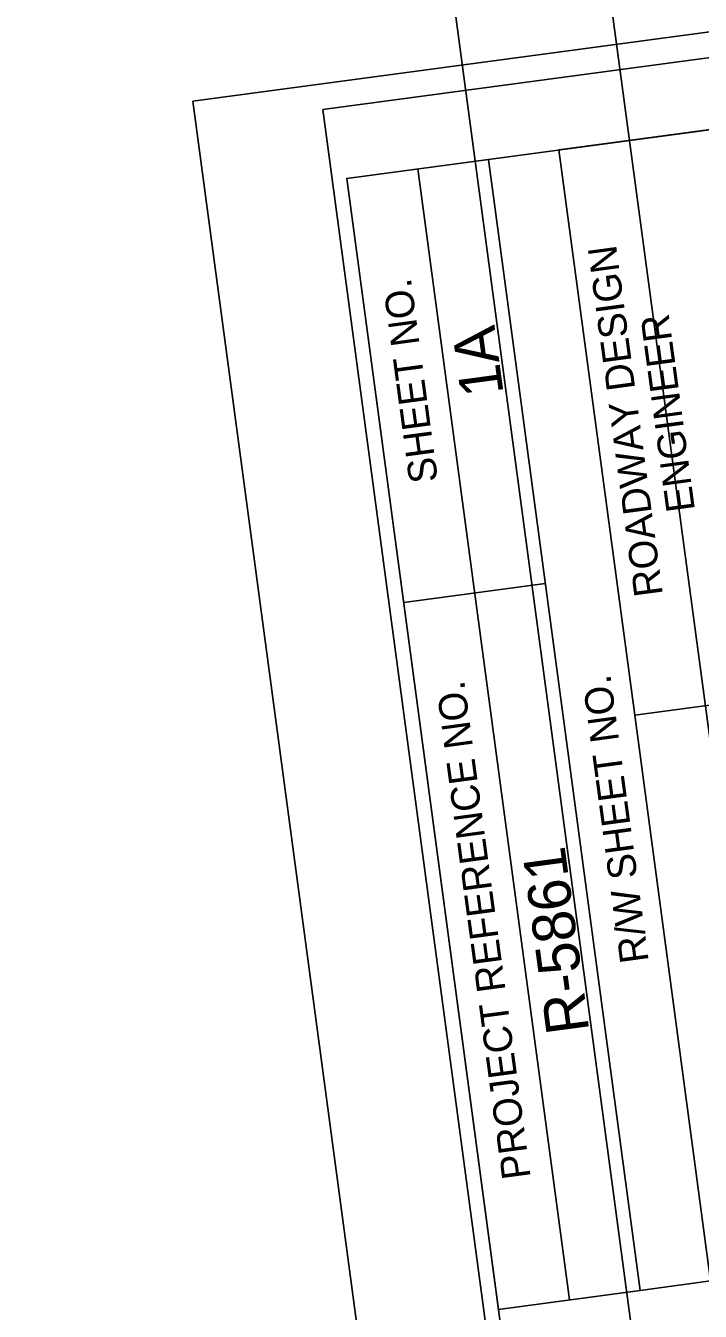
# Model space of a CAD drawing. Extents: x 2573931 to 2578852, y 980053 to 983667.
# Drawn here: x 2573931 to 2574073, y 982712.4 to 982982.8 of the extents above; entities that cross this region are included whole.
import ezdxf

# ---------------------------------------------------------------- set-up
doc = ezdxf.new("R2010")
doc.units = 0
for name, color, linetype in [('Scratch_Level_1', 7, 'Continuous'), ('Sheet Border Standard 30in CELL', 7, 'Continuous'), ('Sheet Data Field CELL', 7, 'Continuous'), ('Sheet Plot Border Inside CELL', 7, 'Continuous'), ('Sheet Plot Border Outside CELL', 7, 'Continuous')]:
    doc.layers.add(name, color=color, linetype=linetype)

msp = doc.modelspace()

# ---------------------------------------------------------------- linework, layer by layer
at = {"layer": 'Scratch_Level_1'}
for p, q in [((2574284.78, 981268.49), (2573963.13, 983666.66)), ((2574252.3, 981264.13), (2573930.99, 983659.79))]:
    msp.add_line(p, q, dxfattribs=at)
at = {"layer": 'Sheet Border Standard 30in CELL'}
for p, q in [((2574060.28, 982716.79), (2574028.37, 982954.72)), ((2574060.28, 982716.79), (2574028.37, 982954.72)), ((2574045.41, 982714.79), (2574013.5, 982952.72)), ((2574010.6, 982861.53), (2574040.33, 982865.52)), ((2574059.19, 982837.78), (2574192.93, 982855.71)), ((2574060.28, 982716.79), (2574075.15, 982718.78))]:
    msp.add_line(p, q, dxfattribs=at)
for points in [[(2573998.57, 982950.72), (2574237.85, 981166.7), (2575486.67, 981334.19), (2575247.39, 983118.21)], [(2574059.19, 982837.78), (2574043.23, 982956.71), (2574177.04, 982974.66), (2574192.99, 982855.72)], [(2574030.49, 982712.79), (2573998.57, 982950.72), (2574028.37, 982954.72), (2574060.28, 982716.79)], [(2574075.15, 982718.78), (2574059.19, 982837.78), (2574192.99, 982855.72), (2574208.95, 982736.73)]]:
    msp.add_lwpolyline(points, close=True, dxfattribs=at)
at = {"layer": 'Sheet Plot Border Inside CELL'}
msp.add_lwpolyline([(2573993.55, 982965.18), (2574259.38, 980983.13), (2575514.27, 981151.44), (2575248.43, 983133.49)], close=True, dxfattribs=at)
at = {"layer": 'Sheet Plot Border Outside CELL'}
msp.add_lwpolyline([(2573966.13, 982966.95), (2574234.76, 980964.09), (2575543.04, 981139.56), (2575274.41, 983142.42)], close=True, dxfattribs=at)

# ---------------------------------------------------------------- texts
at = {"layer": 'Sheet Border Standard 30in CELL'}
for s, height, p in [('ROADWAY DESIGN', 6.0001, (2574065.11, 982863.15)), ('SHEET NO.', 6, (2574017.77, 982887.07)), ('ENGINEER', 6, (2574071.86, 982880.94)), ('PROJECT REFERENCE NO.', 6.0001, (2574037.29, 982740.58)), ('R/W SHEET NO.', 6.0001, (2574062.13, 982786.05))]:
    msp.add_text(s, height=height, rotation=97.639, dxfattribs=at).set_placement(p)
at = {"layer": 'Sheet Data Field CELL'}
for s, p in [('1A', (2574031.58, 982905.47)), ('R-5861', (2574049.63, 982771.37))]:
    msp.add_text(s, height=9, rotation=97.639, dxfattribs=at).set_placement(p)

doc.saveas('drawing.dxf')
